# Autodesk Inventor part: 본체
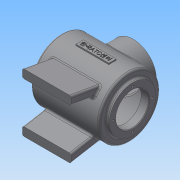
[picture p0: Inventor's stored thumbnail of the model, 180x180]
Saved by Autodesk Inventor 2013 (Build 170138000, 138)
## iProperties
Created: 2015-01
Part Number: 본체
Material: 일반
Document SubType Name: Modeling
Designer: Administrator
Density: 1 g/cm^3
Mass: 376.8 g
Surface Area: 1060.37 cm^2
Volume: 376.8 cm^3
Author: Administrator
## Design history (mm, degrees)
sketch "스케치1"
  geometry: L1 (-56, 50)-(56, 50); L2 (56, 50)-(56, 0); L3 (56, 0)-(-56, 0); L4 (-56, 0)-(-56, 50); 2 further points
  constraints: 8 end point, 2 perpendicular, 1 coincident, 1 horizontal, 1 midpoint, 1 parallel
  dimensions: "d0" = 112 distance of L1.start L1.end; "d2" = 100 diameter of L1 L3
revolve "회전1" sketch "스케치1" stored, may be unused: angle "d3" = 90 deg
sketch "스케치2"
  geometry: C1 r 50 at (0, 0) reference; C2 r 38 at (0, 0)
  constraints: 1 centre point, 1 coincident
  dimensions: "d4" = 76 diameter of C2
extrude "돌출1" join sketch "스케치2" distance "d5" = 5; taper "d6" = 0 deg
node "작업 평면1"
sketch "스케치3"
  geometry: C1 r 38 at (0, 0); 1 further point
  constraints: 1 centre point, 1 coincident
  dimensions: "d8" = 76 diameter of C1
extrude "돌출2" join sketch "스케치3" stored distance "d9" = 5; taper "d10" = 0 deg
sketch "스케치6"
  geometry: L1 (-49, 45)-(48, 45); L2 (48, 45)-(48, 0); L3 (-49, 0)-(-49, 45); L4 (-38, 62)-(38, 62) reference; L5 (-56, 50)-(56, 50) reference; L6 (-56, -50)-(56, -50) reference; L7 (56, -50)-(56, 50) reference; L8 (-56, -50)-(-56, 50) reference; L9 (-49, 0)-(48, 0); 2 further points
  constraints: 8 end point, 2 perpendicular, 1 coincident, 1 horizontal, 1 parallel, 1 point on line
  dimensions: "d12" = 5 distance between parallel lines of L1 L5; "d14" = 8 distance between parallel lines of L7 L2; "d15" = 7 distance between parallel lines of L8 L3
revolve "회전2" sketch "스케치6" stored, may be unused: angle "d16" = 90 deg
sketch "스케치8"
  geometry: C1 r 38 at (0, 0) reference; C2 r 27 at (0, 0)
  constraints: 1 centre point, 1 coincident
  dimensions: "d17" = 54 diameter of C2
extrude "돌출3" cut sketch "스케치8" stored distance "d18" = 5; taper "d19" = 0 deg
sketch "스케치9"
  geometry: C1 r 38 at (0, 0) reference; C2 r 27 at (0, 0)
  constraints: 1 centre point, 1 coincident
  dimensions: "d20" = 54 diameter of C2
extrude "돌출4" cut sketch "스케치9" stored distance "d21" = 5; taper "d22" = 0 deg
sketch "스케치10"
  geometry: C1 r 38 at (0, 0) reference; C2 r 27 at (0, 0)
  constraints: 1 centre point, 1 coincident
  dimensions: "d23" = 54 diameter of C2
extrude "돌출5" cut sketch "스케치10" stored distance "d24" = 5; taper "d25" = 0 deg
sketch "스케치11"
  geometry: C1 r 27 at (0, 0) reference; 1 further point
  constraints: 1 horizontal alignment
  dimensions: "d26" = 32 distance of point (32, 0) C1.centre
hole "구멍1" sketch "스케치11" at (32, 0) diameter "d27" = 3.242; stored, may be unused: countersink angle "d31" = 90 deg, drill point angle "d33" = 118 deg; dims "d28" = 8, "d29" = 4, "d30" = 2, "d32" = 10
sketch "스케치12"
  geometry: C1 r 27 at (0, 0) reference; 1 further point
  constraints: 1 vertical alignment
  dimensions: "d37" = 32 distance of point (0, 32) C1.centre
hole "구멍2" sketch "스케치12" at (0, 32) diameter "d38" = 3.242; stored, may be unused: countersink angle "d42" = 90 deg, drill point angle "d44" = 118 deg; dims "d39" = 8, "d40" = 4, "d41" = 2, "d43" = 10
sketch "스케치16"
  geometry: L1 (-30.865, 39.336)-(-80, 48); L2 (-80, 48)-(-80, 34); L3 (-80, 34)-(-41.901, 27.282); C1 r 27 at (0, 0) reference; C2 r 45 at (0, 0) reference; C3 r 38 at (0, 0) reference; A1 r 50 centre (0, 0) between (-30.865, 39.336) and (-41.901, 27.282) reference; 1 further point
  constraints: 6 end point, 2 point on circle, 1 parallel, 1 vertical
  dimensions: "d49" = 14 distance of L1.end L2.end; "d51" = 80 deg angle of L3 L2; "d53" = 80 distance from line of L2 point (0, 0); "d54" = 48 vertical distance of L1.end point (0, 0)
extrude "돌출6" join sketch "스케치16" stored distance "d55" = 80; taper "d56" = 0 deg
node "작업 평면5"
  node "작업 평면4"
node "작업 평면7"
  node "작업 평면6"
sketch "스케치22"
  geometry: L1 (-26, 6)-(28, 6); L2 (28, 6)-(28, -6); L3 (28, -6)-(-26, -6); L4 (-26, -6)-(-26, 6); L5 (-61, -38)-(-61, 38) reference; 1 further point
  constraints: 8 end point, 2 parallel, 1 horizontal, 1 perpendicular
  dimensions: "d66" = 54 distance of L1.start L1.end; "d68" = 12 distance of L1.end L2.end; "d69" = 6 distance from line of L1 point (0, 0); "d70" = 35 distance between parallel lines of L5 L4
extrude "돌출8" join sketch "스케치22" stored distance "d71" = 6 (= d69); taper "d72" = 0 deg
sketch "스케치23"
  geometry: L1 (-26, 6)-(28, 6) reference; L2 (-61, -38)-(-61, 38) reference; 2 further points
  constraints: 1 other
  dimensions: "d73" = 62 distance from line of L2 point (1, 0); "d74" = 6 distance from line of L1 point (1, 0)
feature "엠보싱1" sketch "스케치23" dims "d0" = 112, "d2" = 100, "d75" = 0.5, "d76" = 0
fillet "모깎기1" dims "d77" = 3
fillet "모깎기2" dims "d78" = 3
chamfer "모따기1" distance "d79" = 1; stored, may be unused: second distance "d80" = 2, angle "d81" = 45 deg
chamfer "모따기2" distance "d82" = 1; stored, may be unused: second distance "d83" = 2, angle "d84" = 45 deg
fillet "모깎기3" dims "d85" = 3
fillet "모깎기4" dims "d86" = 3
sketch "스케치26"
  geometry: 1 further point
node "솔리드1"
mirror "대칭1"
pattern_circular "원형 패턴1" dims angle "d35" = 360 deg
pattern_circular "원형 패턴2" dims angle "d46" = 360 deg
mirror "대칭2"
mirror "대칭3"
node "투영된 루프1"
node "투영된 루프2"
other parameters: "d7" = 62, "d57" = -2, "d65" = 2
